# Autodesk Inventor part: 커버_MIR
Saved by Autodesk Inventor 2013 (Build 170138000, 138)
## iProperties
Created: 2014-03
Part Number: 커버_MIR
Material: 일반
Document SubType Name: Modeling
Designer: H1
Density: 1 g/cm^3
Author: SeoGD™[esajin.kr]
d0: 6.000 mm
d1: 0.00 deg
d2: 3.000 mm
d3: 0.00 deg
d4: 3.400 mm
d6: 6.000 mm
d7: 3.300 mm
d11: 32.000 mm
d12: 4.000 mm
d13: 0.00 deg
d14: 2.000 mm
d17: 18.000 mm
d19: 25.000 mm
d20: 7.500 mm
d27: 4.000 ul
d28: 360.00 deg
d30: 1.600 mm
d32: 30.00 deg
d33: 0.300 mm
d34: 23.000 mm
d35: 2.000 mm
d36: 0.00 deg
d37: 3.000 mm
d38: 0.500 mm
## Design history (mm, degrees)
derived "커버.ipt"
  sketch "스케치1"
    geometry: C1 r 25 at (0, 0) reference; C2 r 16 at (0, 0) reference; 1 further point
  sketch "스케치2"
    geometry: C1 r 1.23 at (0, 20.5) reference; 1 further point
  sketch "스케치3"
    geometry: C1 r 16 at (0, 0) reference; 1 further point
  sketch "스케치4"
    geometry: C1 r 16 at (0, 0) reference; C2 r 11.5 at (0, 0) reference; 1 further point
feature "솔리드1::커버.ipt"
tag "피쳐 태그1"
node "솔리드1"
other parameters: "d0" = 10, "d0_1" = 6, "d1" = 0 deg, "d2" = 3, "d3" = 0 deg, "d4" = 3.4, "d6" = 6, "d7" = 3.3, "d11" = 32, "d12" = 4, "d13" = 0 deg, "d14" = 2, "d17" = 18, "d19" = 25, "d20" = 7.5, "d27" = 4, "d28" = 360 deg, "d30" = 1.6, "d32" = 30 deg, "d33" = 0.3, "d34" = 23, "d35" = 2, "d36" = 0 deg, "d37" = 3, "d38" = 0.5
